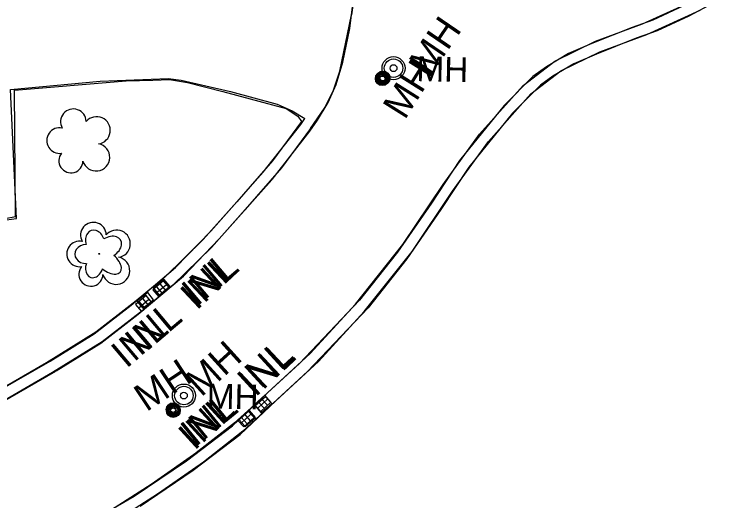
# Model space of a CAD drawing. Extents: x 588843 to 2552415, y 180129 to 269402.
# Drawn here: x 595101 to 595256.1, y 184366.4 to 184472 of the extents above; entities that cross this region are included whole.
import ezdxf

# ---------------------------------------------------------------- set-up
doc = ezdxf.new("R2010")
doc.units = 0
for name, color, linetype in [('E_DRN', 7, 'Continuous'), ('E_DRN_Text', 7, 'Continuous'), ('E_DWY', 7, 'Continuous'), ('E_LAND_Vegetation', 7, 'Continuous'), ('E_RDWY_C_and_G', 7, 'Continuous'), ('E_UTL_MH', 7, 'Continuous'), ('E_UTL_MH_Text', 7, 'Continuous'), ('E_UTL_SAN', 7, 'Continuous'), ('Level 11', 7, 'Continuous'), ('Level 15', 7, 'Continuous'), ('Level 16', 7, 'Continuous'), ('Level 17', 7, 'Continuous'), ('Level 18', 7, 'Continuous')]:
    doc.layers.add(name, color=color, linetype=linetype)

# ---------------------------------------------------------------- blocks, each defined once
blk = doc.blocks.new('MH')
at = {"layer": 'E_UTL_MH'}
for radius in [5, 4, 1.5]:
    blk.add_circle((0, 0), radius, dxfattribs=at)
blk.add_text('MH', height=10.8, dxfattribs=at).set_placement((10, -5.4))
blk = doc.blocks.new('MHO_3')
at = {"layer": 'E_UTL_MH'}
for centre, radius in [((0.3, -0.4), 9.84), ((0.3, -0.4), 7.98), ((0.2, -0.5), 6.35), ((0.1, -0.5), 3.97)]:
    blk.add_circle(centre, radius, dxfattribs=at)
blk = doc.blocks.new('MHT_3')
at = {"layer": 'E_UTL_MH_Text'}
blk.add_text('MH', height=39.37, dxfattribs=at).set_placement((-32.2, -19.7))
blk = doc.blocks.new('INLO_3')
at = {"layer": 'E_DRN'}
for p, q in [((6.6, -13.1), (6.6, 0)), ((13.1, -13.1), (13.1, 0)), ((19.7, -6.6), (0, -6.6))]:
    blk.add_line(p, q, dxfattribs=at)
blk.add_lwpolyline([(0, -13.1), (19.7, -13.1), (19.7, 0), (0, 0)], close=True, dxfattribs=at)
blk = doc.blocks.new('INLT_20_1')
at = {"layer": 'E_DRN_Text'}
blk.add_text('INL', height=39.37, dxfattribs=at).set_placement((-36.2, -19.7))
blk = doc.blocks.new('INLT_15_1')
at = {"layer": 'E_DRN_Text'}
blk.add_text('INL', height=39.37, dxfattribs=at).set_placement((-36.2, -19.7))
blk = doc.blocks.new('DTRE_4')
at = {"layer": 'E_LAND_Vegetation'}
blk.add_circle((-0.6, 0), 0.601, dxfattribs=at)
for centre, major_axis, ratio in [((-6.1, 17.5), (4.5, -16.3), 0.782863), ((13.3, 9), (-17.3, -9.6), 0.691916), ((-19.3, 0.5), (16.2, -0.4), 0.832022), ((11.6, -12.2), (-16.4, 15), 0.560249), ((-8.2, -17.2), (5.9, 15.9), 0.716896)]:
    blk.add_ellipse(centre, major_axis=major_axis, ratio=ratio, start_param=1.570796, end_param=4.712389, dxfattribs=at)

msp = doc.modelspace()

# ---------------------------------------------------------------- linework, layer by layer
at = {"layer": 'E_DWY'}
msp.add_lwpolyline([(595088.4, 184425.96), (595101.51, 184427.72), (595100.2, 184455.68), (595119.69, 184457.51), (595134.43, 184458.11), (595137.29, 184457.72), (595147.98, 184455.24), (595158.09, 184452.52), (595161.39, 184451.08), (595164.09, 184449.36)], dxfattribs=at)
at = {"layer": 'E_RDWY_C_and_G'}
for points in [[(595157.04, 184436.19), (595165.23, 184446.62), (595166.88, 184449), (595169.16, 184452.9), (595170.91, 184456.81), (595172.37, 184461.61), (595173.88, 184468.9), (595174.52, 184474.22), (595174.95, 184479.96), (595174.77, 184483.73), (595173.74, 184488.81)], [(595256.14, 184476.28), (595247.45, 184471.63), (595240.6, 184468.41), (595236.05, 184466.81), (595227.4, 184463.39), (595222.5, 184461.27), (595217.94, 184458.55), (595215.25, 184456.63), (595209.23, 184450.52), (595199.71, 184438.82), (595193.65, 184429.64), (595186.23, 184418.9), (595177.84, 184408.32), (595164.73, 184394.45), (595150.66, 184381.56), (595142.11, 184374.82)], [(595246.33, 184473.86), (595239.65, 184470.73), (595235.18, 184469.16), (595226.44, 184465.7), (595221.36, 184463.5), (595216.57, 184460.64), (595213.62, 184458.54), (595207.37, 184452.19), (595197.69, 184440.31), (595191.58, 184431.04), (595184.22, 184420.39), (595175.95, 184409.96), (595162.97, 184396.23), (595149.04, 184383.47), (595140.56, 184376.79)], [(595155.07, 184437.73), (595163.22, 184448.11), (595164.09, 184449.36)], [(595108.85, 184396.75), (595118.41, 184402.69), (595126.39, 184408.86), (595136.06, 184417.03), (595143.71, 184424.95), (595155.1, 184437.76)], [(595110.17, 184394.62), (595119.84, 184400.63), (595127.97, 184406.92), (595137.77, 184415.2), (595145.55, 184423.25), (595156.96, 184436.1)], [(594941.11, 184383.77), (594953.78, 184378.89), (594963.26, 184375.72), (594970.64, 184373.86), (594983.05, 184371.31), (594991.5, 184369.98), (595000.61, 184369.17), (595013.47, 184368.96), (595024.75, 184369.29), (595031.2, 184369.64), (595040.25, 184370.8), (595054.06, 184373.61), (595067.8, 184377.25), (595082.11, 184382.58), (595094.67, 184388.61), (595108.85, 184396.75)], [(594940.21, 184381.44), (594952.94, 184376.53), (594962.55, 184373.32), (594970.08, 184371.43), (594982.6, 184368.85), (594991.19, 184367.49), (595000.48, 184366.67), (595013.49, 184366.46), (595024.85, 184366.79), (595031.43, 184367.15), (595040.66, 184368.33), (595054.63, 184371.17), (595068.56, 184374.86), (595083.09, 184380.28), (595095.84, 184386.39), (595110.09, 184394.58)], [(595140.67, 184376.87), (595130.77, 184369.94), (595121.15, 184363.82), (595113.33, 184359.57), (595101.45, 184354.24)], [(595142.11, 184374.82), (595132.16, 184367.86), (595122.42, 184361.66), (595114.44, 184357.33), (595102.47, 184351.96)]]:
    msp.add_lwpolyline(points, dxfattribs=at)
at = {"layer": 'Level 11'}
for points in [[(595116.22, 184361.1), (595127.04, 184367.39), (595138.44, 184375.08), (595148.45, 184382.68), (595156.08, 184389.9), (595165.28, 184398.41), (595175.1, 184409.09), (595185.38, 184422.03), (595194.14, 184435.05), (595202.01, 184446), (595211.48, 184456.58), (595218.4, 184461.87), (595227.21, 184466.17), (595237.42, 184469.96), (595248.77, 184475.16)], [(595174.58, 184474.45), (595174.28, 184471.87)], [(595128.37, 184365.27), (595139.9, 184373.04), (595150.07, 184380.77), (595157.79, 184388.08), (595167.06, 184396.64), (595177, 184407.47), (595187.4, 184420.55), (595196.19, 184433.62), (595203.96, 184444.43), (595213.19, 184454.73), (595219.72, 184459.73), (595228.19, 184463.87), (595238.37, 184467.65), (595249.92, 184472.93)], [(595165.37, 184447.26), (595168.53, 184451.86), (595170.37, 184455.54), (595171.71, 184459.65), (595174.28, 184471.87)], [(595163.36, 184448.74), (595157.09, 184440.22), (595149.33, 184431.32), (595142.04, 184423.12), (595133.82, 184415.06), (595127.52, 184409.82), (595118.72, 184402.98), (595108.04, 184396.38), (595095.75, 184389.27), (595084.08, 184383.45), (595069.02, 184378.08), (595055.31, 184374.2), (595040.62, 184370.76), (595027.88, 184369.5), (595020.28, 184369.11), (595011.01, 184369.29)], [(595165.37, 184447.26), (595159.04, 184438.66), (595151.2, 184429.67), (595143.85, 184421.39), (595135.49, 184413.21), (595129.09, 184407.87), (595120.15, 184400.92), (595109.32, 184394.23), (595096.93, 184387.07), (595085.06, 184381.14), (595069.78, 184375.7), (595055.94, 184371.78), (595041.03, 184368.29), (595028.06, 184367), (595020.32, 184366.61), (595010.96, 184366.79)]]:
    msp.add_lwpolyline(points, dxfattribs=at)
at = {"layer": 'Level 15'}
for points in [[(595134.8, 184413.01), (595133.52, 184414.54), (595131.22, 184412.61), (595132.5, 184411.08), (595134.8, 184413.01)], [(595131.26, 184410.07), (595130.01, 184411.63), (595127.67, 184409.75), (595128.92, 184408.19), (595131.26, 184410.07)], [(595153.34, 184387.02), (595154.66, 184385.52), (595156.92, 184387.5), (595155.6, 184389), (595153.34, 184387.02)], [(595149.85, 184384.02), (595151.17, 184382.51), (595153.43, 184384.48), (595152.11, 184385.99), (595149.85, 184384.02)]]:
    msp.add_lwpolyline(points, dxfattribs=at)
at = {"layer": 'Level 16'}
for centre, radius in [((595181.08, 184458.18), 1.5), ((595181.08, 184458.18), 1.22), ((595181.08, 184458.17), 0.968), ((595181.05, 184458.16), 0.605), ((595135.55, 184386.21), 1.5), ((595135.56, 184386.21), 1.22), ((595135.55, 184386.2), 0.968), ((595135.52, 184386.19), 0.605)]:
    msp.add_circle(centre, radius, dxfattribs=at)
at = {"layer": 'Level 17'}
msp.add_lwpolyline([(595011.37, 184404.06), (595024.33, 184404.64), (595036.32, 184406.45), (595041.77, 184408.54), (595059.27, 184415.7), (595085.4, 184424.21), (595091.69, 184425.93), (595096.76, 184427.27), (595101.28, 184428.15), (595101.08, 184455.57), (595125.34, 184457.55), (595131.15, 184457.75), (595134.71, 184457.86), (595138.62, 184457.22), (595146.3, 184455.29), (595160.03, 184451.56), (595162.59, 184449.88), (595163.36, 184448.74)], dxfattribs=at)
at = {"layer": 'Level 18'}
for centre, radius, start, end in [((595113.87, 184448.68), 2.78, 1.3946, 209.1675), ((595118.91, 184446.82), 2.97, 278.4237, 139.6575), ((595110.87, 184444.61), 2.78, 78.0716, 279.0826), ((595118.8, 184440.97), 2.97, 196.0745, 79.0477), ((595113.33, 184440.21), 2.61, 140.7797, 358.7123), ((595118.22, 184424.07), 2.78, 1.3946, 209.1675), ((595123.26, 184422.21), 2.97, 278.4237, 139.6575), ((595115.22, 184420), 2.78, 78.0716, 279.0826), ((595123.15, 184416.36), 2.97, 196.0745, 79.0477), ((595117.68, 184415.6), 2.61, 140.7797, 358.7123)]:
    msp.add_arc(centre, radius, start, end, dxfattribs=at)

# ---------------------------------------------------------------- block references
at = {"layer": 'E_DRN'}
for p, xscale, yscale, rotation in [((595134.72, 184412.63), 0.1524003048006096, 0.15240030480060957, -139.8103924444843), ((595130.93, 184409.43), 0.15240030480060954, 0.15240030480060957, -139.80914055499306), ((595153.2, 184387.29), 0.15240030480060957, 0.1524003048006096, 42.500443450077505), ((595149.53, 184383.92), 0.15240030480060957, 0.15240030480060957, 42.50442671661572)]:
    msp.add_blockref('INLO_3', p, dxfattribs=dict(at, xscale=xscale, yscale=yscale, rotation=rotation))
at = {"layer": 'E_DRN_Text'}
for name, p, xscale, yscale, rotation in [('INLT_20_1', (595142.93, 184414.31), 0.1524003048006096, 0.15240030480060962, 40.18960755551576), ('INLT_20_1', (595127.64, 184400.86), 0.15240030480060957, 0.1524003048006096, 40.19085944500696), ('INLT_15_1', (595154.94, 184395.03), 0.15240030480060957, 0.1524003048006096, 42.500443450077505), ('INLT_15_1', (595142.17, 184383.12), 0.15240030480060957, 0.15240030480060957, 42.50442671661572)]:
    msp.add_blockref(name, p, dxfattribs=dict(at, xscale=xscale, yscale=yscale, rotation=rotation))
at = {"layer": 'E_LAND_Vegetation', "xscale": 0.1524003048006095, "yscale": 0.15240030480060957, "rotation": 2.3276622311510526}
msp.add_blockref('DTRE_4', (595119.59, 184420.01), dxfattribs=at)
at = {"layer": 'E_UTL_MH', "xscale": 0.1524003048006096}
for p, yscale, rotation in [((595180.87, 184458.04), 0.1524003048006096, 55.71038961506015), ((595135.49, 184386.01), 0.15240030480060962, 42.17707611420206)]:
    msp.add_blockref('MHO_3', p, dxfattribs=dict(at, yscale=yscale, rotation=rotation))
at = {"layer": 'E_UTL_MH_Text', "xscale": 0.1524003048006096}
for p, yscale, rotation in [((595191.61, 184464.17), 0.1524003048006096, 55.71038961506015), ((595143.25, 184394.3), 0.15240030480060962, 42.17707611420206)]:
    msp.add_blockref('MHT_3', p, dxfattribs=dict(at, yscale=yscale, rotation=rotation))
at = {"layer": 'E_UTL_SAN', "xscale": 0.500001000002, "yscale": 0.5000010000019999, "rotation": -1.2027594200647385}
for p in [(595183.37, 184460.32), (595137.86, 184389.26)]:
    msp.add_blockref('MH', p, dxfattribs=at)

# ---------------------------------------------------------------- texts
at = {"layer": 'Level 15'}
for rotation, p in [(43.1944, (595140.63, 184407.61)), (39.958, (595128.32, 184397.61)), (43.1944, (595153.37, 184388.77)), (39.2363, (595140.33, 184377.98))]:
    msp.add_text('INL', height=6, rotation=rotation, dxfattribs=at).set_placement(p)
at = {"layer": 'Level 16'}
for rotation, p in [(57.8788, (595185.82, 184448.94)), (33.5754, (595129.71, 184385.61))]:
    msp.add_text('MH', height=6, rotation=rotation, dxfattribs=at).set_placement(p)

doc.saveas('drawing.dxf')
